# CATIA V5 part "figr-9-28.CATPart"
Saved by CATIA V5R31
Part number: Part1
Bounding box of the stored display mesh (mm): x -75 to 75, y -50 to 50, z 0 to 40
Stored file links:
  D:\PROJECTS\Project 2021\US EDITION\CATIA V5 6R 2021\Resources\Part Files\c09_catia_v5_6r2021_prt\c09_catia_v5_6r2021_prt\figr-9-28.CATPart
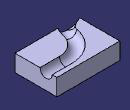
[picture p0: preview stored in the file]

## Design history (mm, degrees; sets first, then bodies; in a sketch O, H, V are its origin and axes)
Body1 (main body)
  Sketch1 on xy-plane, origin (0, 0, 0), H (1, 0, 0), V (0, 1, 0)
    line L1 (-75, 50) -> (75, 50)
    line L2 (75, 50) -> (75, -50)
    line L3 (75, -50) -> (-75, -50)
    line L4 (-75, -50) -> (-75, 50)
    axis line L5 (75, -50) -> (-75, 50)
    length L2 = 100
    length L3 = 150
    horizontal: L1 H, L3 H
    vertical: L2 V, L4 V
    midpoint: O L5
  Pad1: profile Sketch1, direction (0, 0, 1), length 40
  Sketch2 on face of Pad1, origin (75, 0, 0), H (0, 1, 0), V (0, 0, 1)
    arc A1 centre (24.1478, 40) radius 14.6047 from (9.543, 40) to (38.7525, 40) ccw
    point P1 (24.1478, 40)
    reference projected point E1 (24.1478, 40) from vertex of Sketch3
    line L1 (9.543, 40) -> (38.7525, 40)
    coincidence: P1 E1
    horizontal: L1 H
  Sketch3 on face of Pad1, origin (0, 0, 40), H (1, 0, 0), V (0, 1, 0)
    point P1 (75, 24.1478)
    line L1 (75, 24.1478) -> (28.6577, 24.1478)
    arc A1 centre (28.6577, -39.2062) radius 63.354 from (28.6577, 24.1478) to (-33.8383, -28.8149) ccw
    arc A2 centre (-62.192, -24.1005) radius 28.7429 from (-33.8383, -28.8149) to (-49.7271, -50) cw
    point P6 (-49.7271, -50)
    reference projected line E1 (75, -50) -> (75, 50) from edge [face of Pad1 | face of Pad1]
    reference projected line E2 (-75, -50) -> (75, -50) from edge [face of Pad1 | face of Pad1]
    horizontal: L1 H
    tangency: A1 L1, A2 A1
    coincidence: P1 E1, P6 E2
  Slot1: profile Sketch2, centre curve Sketch3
